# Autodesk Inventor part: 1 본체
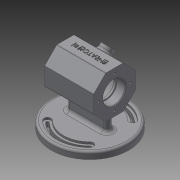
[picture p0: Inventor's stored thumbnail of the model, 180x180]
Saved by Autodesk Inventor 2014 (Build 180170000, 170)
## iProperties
Created: 2017-06
Part Number: 1 본체
Material: Generic
Document SubType Name: Modeling
Designer: Administrator
Density: 1 g/cm^3
Appearance: Default
Author: Administrator
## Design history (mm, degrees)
sketch "스케치1"
  geometry: C1 r 55 at (0, 0); 1 further point
  constraints: 1 centre point, 1 coincident
  dimensions: "d0" = 110 diameter of C1
extrude "돌출1" new body sketch "스케치1" distance "d2" = 7; taper "d3" = 0 deg
sketch "스케치2"
  geometry: L1 (0, 70.091)-(0, -70.669); L2 (-66.722, 0)-(72.691, 0); L3 (-64.441, 64.441)-(59.225, -59.225); L4 (60.185, 60.185)-(-55.495, -55.495); C1 r 55 at (0, 0) reference; A1 r 43 centre (0, 0) between (-30.406, -30.406) and (30.406, -30.406); A2 r 5 centre (-30.406, -30.406) between (-26.87, -26.87) and (-33.941, -33.941); A3 r 5 centre (30.406, -30.406) between (33.941, -33.941) and (26.87, -26.87); A4 r 38 centre (0, 0) between (-26.87, -26.87) and (26.87, -26.87); A5 r 48 centre (0, 0) between (-33.941, -33.941) and (33.941, -33.941); A6 r 2 centre (30.406, -30.406) between (31.82, -31.82) and (28.991, -28.991); A7 r 45 centre (0, 0) between (-31.82, -31.82) and (31.82, -31.82); A8 r 2 centre (-30.406, -30.406) between (-28.991, -28.991) and (-31.82, -31.82); A9 r 41 centre (0, 0) between (-28.991, -28.991) and (28.991, -28.991); A10 r 38 centre (0, 0) between (26.87, 26.87) and (-26.87, 26.87); A11 r 5 centre (30.406, 30.406) between (26.87, 26.87) and (33.941, 33.941); A12 r 41 centre (0, 0) between (28.991, 28.991) and (-28.991, 28.991); A13 r 45 centre (0, 0) between (31.82, 31.82) and (-31.82, 31.82); A14 r 48 centre (0, 0) between (33.941, 33.941) and (-33.941, 33.941); A15 r 2 centre (30.406, 30.406) between (28.991, 28.991) and (31.82, 31.82); A16 r 5 centre (-30.406, 30.406) between (-33.941, 33.941) and (-26.87, 26.87); A17 r 2 centre (-30.406, 30.406) between (-31.82, 31.82) and (-28.991, 28.991); 1 further point
  constraints: 34 point on circle, 17 centre point, 10 symmetric about line, 8 end point, 7 point on line, 3 coincident, 1 midpoint, 1 perpendicular, 1 vertical, 11 other
  dimensions: "d7" = 45 deg angle of L1 L3; "d8" = 45 deg angle of L1 L4; "d9" = 10 diameter of A3; "d12" = 10 diameter of A2; "d13" = 2 radius of A6
extrude "돌출2" cut sketch "스케치2" distance "d14" = 7; taper "d15" = 0 deg
sketch "스케치3"
  geometry: C1 r 55 at (0, 0) reference; C2 r 55 at (0, 0); A1 r 41 centre (0, 0) between (-28.991, -28.991) and (28.991, -28.991) reference; A2 r 2 centre (30.406, -30.406) between (31.82, -31.82) and (28.991, -28.991) reference; A3 r 45 centre (0, 0) between (-31.82, -31.82) and (31.82, -31.82) reference; A4 r 2 centre (-30.406, -30.406) between (-28.991, -28.991) and (-31.82, -31.82) reference; A5 r 2 centre (30.406, 30.406) between (28.991, 28.991) and (31.82, 31.82) reference; A6 r 41 centre (0, 0) between (28.991, 28.991) and (-28.991, 28.991) reference; A7 r 2 centre (-30.406, 30.406) between (-31.82, 31.82) and (-28.991, 28.991) reference; A8 r 45 centre (0, 0) between (31.82, 31.82) and (-31.82, 31.82) reference; A9 r 38 centre (0, 0) between (26.87, 26.87) and (-26.87, 26.87); A10 r 5 centre (30.406, 30.406) between (26.87, 26.87) and (33.941, 33.941); A11 r 48 centre (0, 0) between (33.941, 33.941) and (-33.941, 33.941); A12 r 5 centre (-30.406, 30.406) between (-33.941, 33.941) and (-26.87, 26.87); A13 r 38 centre (0, 0) between (-26.87, -26.87) and (26.87, -26.87); A14 r 5 centre (-30.406, -30.406) between (-26.87, -26.87) and (-33.941, -33.941); A15 r 48 centre (0, 0) between (-33.941, -33.941) and (33.941, -33.941); A16 r 5 centre (30.406, -30.406) between (33.941, -33.941) and (26.87, -26.87)
  constraints: 16 point on circle, 9 centre point, 1 coincident, 1 concentric, 6 other
  dimensions: "d16" = 5 radius of A12; "d17" = 5 radius of A14
extrude "돌출3" join sketch "스케치3" distance "d18" = 3; taper "d19" = 0 deg
sketch "스케치10" dims "d66" = 60
  geometry: L1 (-44.95, 62)-(50.167, 62); L2 (-55, 0)-(55, 0) reference; L3 (30, 49.574)-(12.426, 32); L4 (12.426, 32)-(-12.426, 32); L5 (-12.426, 32)-(-30, 49.574); L6 (-30, 49.574)-(-30, 74.426); L7 (-30, 74.426)-(-12.426, 92); L8 (-12.426, 92)-(12.426, 92); L9 (12.426, 92)-(30, 74.426); L10 (30, 74.426)-(30, 49.574); 5 further points
  constraints: 18 end point, 2 horizontal alignment, 2 midpoint, 1 coincident, 1 horizontal, 1 point on line, 1 vertical alignment, 19 other
  dimensions: "d65" = 62 distance between parallel lines of L2 L1
extrude "돌출7" join sketch "스케치10" stored distance "d67" = 70; taper "d68" = 0 deg
sketch "스케치11"
  geometry: L1 (-24, 0)-(24, 0); L2 (-24, 5)-(24, 5); L3 (24, -5)-(-24, -5); A1 r 48 centre (0, 0) between (-33.941, -33.941) and (33.941, -33.941) reference; A2 r 5 centre (-24, 0) between (-24, 5) and (-24, -5); A3 r 5 centre (24, 0) between (24, -5) and (24, 5); 1 further point
  constraints: 8 end point, 4 point on circle, 4 tangent, 2 centre point, 1 coincident, 1 horizontal, 1 midpoint, 1 parallel
  dimensions: "d69" = 48 distance of L1.end L1.start; "d70" = 5 radius of A3
extrude "돌출8" join sketch "스케치11" stored distance "d71" = 70; taper "d72" = 0 deg
sketch "스케치12"
  geometry: L1 (-35, 74.426)-(-35, 49.574) reference; L2 (35, 49.574)-(35, 74.426) reference; L3 (-54.155, 62)-(63.053, 62); L4 (-35, 62)-(-35, 78); L5 (-35, 78)-(-23, 78); L6 (-23, 78)-(-23, 76); L7 (-23, 76)-(-20, 76); L8 (-20, 76)-(-20, 87); L9 (-20, 87)-(20, 87); L10 (20, 87)-(20, 76); L11 (20, 76)-(23, 76); L12 (23, 76)-(23, 78); L13 (23, 78)-(35, 78); L14 (35, 78)-(35, 62); L15 (-35, 62)-(35, 62); L16 (35, 62)-(35, 78); 1 further point
  constraints: 28 end point, 7 perpendicular, 5 parallel, 2 midpoint, 2 point on line, 1 collinear
  dimensions: "d73" = 62 distance from line of point (0, 0) L3; "d74" = 32 diameter of L5 L3; "d75" = 12 distance of L4.end L5.end; "d76" = 28 diameter of L7 L3; "d77" = 3 distance of L6.end L7.end; "d78" = 40 distance of L8.end L9.end; "d79" = 50 diameter of L9 L3; "d80" = 3 distance of L10.end L11.end; "d81" = 28 diameter of L11 L3; "d82" = 32 diameter of L13 L3
revolve "회전2" sketch "스케치12" stored, may be unused: angle "d83" = 90 deg
node "작업 평면2"
sketch "스케치13"
  geometry: C1 r 8 at (35, 11.47); 1 further point
  constraints: 1 centre point, 1 vertical alignment
  dimensions: "d85" = 16 diameter of C1
extrude "돌출9" join sketch "스케치13" stored distance "d86" = 70; taper "d87" = 0 deg
sketch "스케치14"
  geometry: L1 (0, 0)-(0, 24.853) reference; L2 (70, 42.426)-(0, 42.426) reference; 2 further points
  constraints: 1 other
  dimensions: "d88" = 35 distance from line of point (35, 12.426) L1; "d89" = 30 distance from line of L2 point (35, 12.426)
feature "엠보싱1" sketch "스케치14" dims "d90" = 0.5, "d91" = 0
fillet "모깎기1" dims "d92" = 1
fillet "모깎기2" dims "d93" = 5
fillet "모깎기3" dims "d94" = 3
chamfer "모따기1" distance "d95" = 1; stored, may be unused: second distance "d96" = 2, angle "d97" = 45 deg
hole "구멍2" diameter "d100" = 8; stored, may be unused: countersink angle "d104" = 90 deg, drill point angle "d106" = 0 deg; dims "d98" = 10, "d99" = 10, "d101" = 8, "d102" = 4, "d103" = 2, "d105" = 28.25
chamfer "모따기2" distance "d107" = 1; stored, may be unused: second distance "d108" = 2, angle "d109" = 45 deg
sketch "스케치15" dims "d110" = 46
  geometry: C1 r 17 at (-62, 0) reference; 3 further points
  constraints: 1 coincident, 1 horizontal alignment, 2 other
hole "구멍3" sketch "스케치15" at (-85, 0) diameter "d111" = 3.242; stored, may be unused: countersink angle "d115" = 90 deg, drill point angle "d117" = 118 deg; dims "d112" = 8, "d113" = 4, "d114" = 2, "d116" = 10
node "솔리드1"
pattern_circular "원형 패턴2" dims angle "d119" = 360 deg
mirror "대칭2"
other parameters: "d4" = 96, "d6" = 76, "d84" = 7
